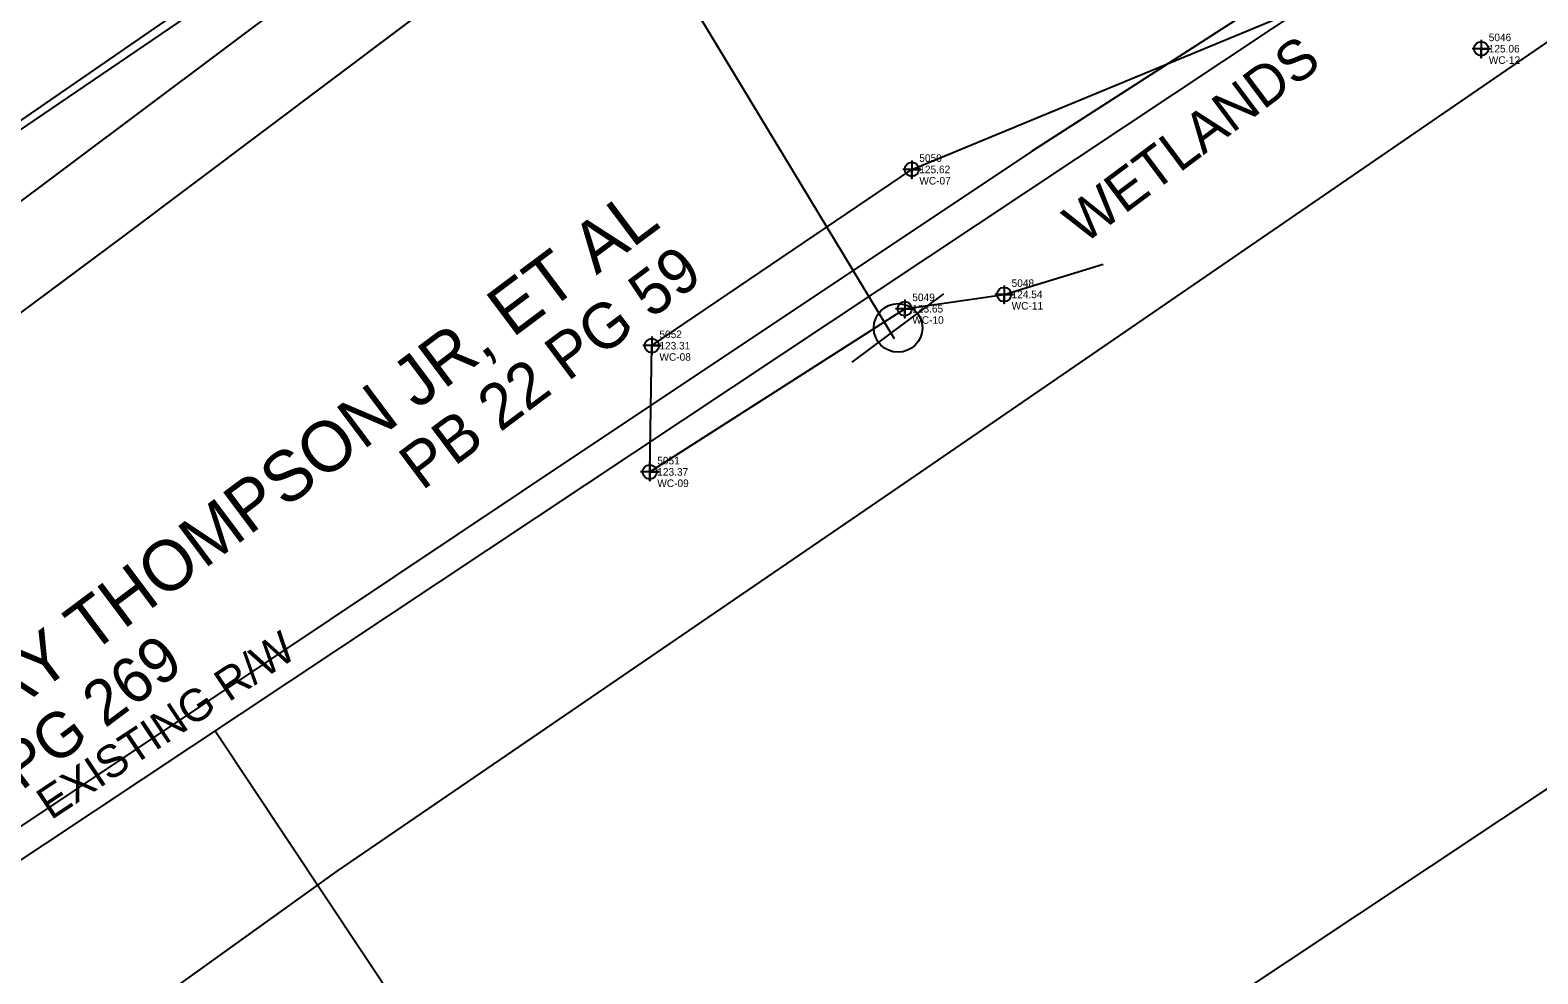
# Model space of a CAD drawing. Extents: x 2186615 to 2188822, y 629899 to 631820.
# Drawn here: x 2188154.1 to 2188303.7, y 631026.2 to 631119.9 of the extents above; entities that cross this region are included whole.
import ezdxf

# ---------------------------------------------------------------- set-up
doc = ezdxf.new("R2010")
doc.units = 0
for name, color, linetype in [('Exist Environmental Wetland Boundary', 7, 'Continuous'), ('Exist Environmental Wetland Boundary Cogo Comment', 7, 'Continuous'), ('Exist Environmental Wetland Boundary Cogo Elevation', 7, 'Continuous'), ('Exist Environmental Wetland Boundary Cogo Number', 7, 'Continuous'), ('Exist Environmental Wetland Boundary Cogo Point CELL', 7, 'Continuous'), ('Exist Environmental Wetland Boundary Text', 7, 'Continuous'), ('Exist Property Deed Book Text', 7, 'Continuous'), ('Exist Property Owner Text', 7, 'Continuous'), ('Exist Railroads Standard Gauge', 7, 'Continuous'), ('Exist Right of Way Line', 7, 'Continuous'), ('Exist Right of Way Line Text', 7, 'Continuous'), ('Exist Right of Way Width CELL', 7, 'Continuous'), ('Exist Roads EOP Text', 7, 'Continuous'), ('Exist Utilities Sanitary Sewer Forced Main SUE LOS B', 7, 'Continuous'), ('Exist Utilities Telephone Pole CELL', 7, 'Continuous'), ('Exist Utilities Telephone UG Cable SUE LOS C', 7, 'Continuous'), ('Exist Vegetation Woods Line', 7, 'Continuous'), ('Scratch_Level_1', 7, 'Continuous')]:
    doc.layers.add(name, color=color, linetype=linetype)

msp = doc.modelspace()

# ---------------------------------------------------------------- linework, layer by layer
at = {"layer": 'Exist Environmental Wetland Boundary'}
for points in [[(2188215.58, 631076.01), (2188215.79, 631088.55), (2188241.59, 631106.05), (2188283.04, 631123.21), (2188321.67, 631142.56)], [(2188215.58, 631076.01), (2188240.89, 631092.22), (2188250.75, 631093.63), (2188260.58, 631096.63)]]:
    msp.add_lwpolyline(points, dxfattribs=at)
at = {"layer": 'Exist Environmental Wetland Boundary Cogo Point CELL'}
for points in [[(2188298.11, 631118.93), (2188298.11, 631117.13), (2188298.11, 631118.03), (2188299.01, 631118.03), (2188297.21, 631118.03)], [(2188241.59, 631106.95), (2188241.59, 631105.15), (2188241.59, 631106.05), (2188242.49, 631106.05), (2188240.69, 631106.05)], [(2188250.75, 631094.53), (2188250.75, 631092.73), (2188250.75, 631093.63), (2188251.65, 631093.63), (2188249.85, 631093.63)], [(2188240.89, 631093.12), (2188240.89, 631091.32), (2188240.89, 631092.22), (2188241.79, 631092.22), (2188239.98, 631092.22)], [(2188215.79, 631089.45), (2188215.79, 631087.65), (2188215.79, 631088.55), (2188216.69, 631088.55), (2188214.89, 631088.55)], [(2188215.58, 631076.91), (2188215.58, 631075.11), (2188215.58, 631076.01), (2188216.48, 631076.01), (2188214.68, 631076.01)]]:
    msp.add_lwpolyline(points, dxfattribs=at)
for centre in [(2188298.11, 631118.03), (2188241.59, 631106.05), (2188250.75, 631093.63), (2188240.89, 631092.22), (2188215.79, 631088.55), (2188215.58, 631076.01)]:
    msp.add_circle(centre, 0.703, dxfattribs=at)
at = {"layer": 'Exist Railroads Standard Gauge'}
msp.add_line((2187893.71, 630771.38), (2188414.52, 631117.54), dxfattribs=at)
at = {"layer": 'Exist Right of Way Line'}
for p, q in [((2187154.4, 630354.1), (2188538.85, 631392.04)), ((2187850.54, 630836.34), (2188624.63, 631350.85)), ((2187850.54, 630836.34), (2188371.34, 631182.5)), ((2187850.54, 630836.34), (2188371.34, 631182.5))]:
    msp.add_line(p, q, dxfattribs=at)
at = {"layer": 'Exist Right of Way Width CELL'}
msp.add_line((2188172.46, 631050.31), (2188198.28, 631011.45), dxfattribs=at)
at = {"layer": 'Exist Utilities Sanitary Sewer Forced Main SUE LOS B'}
msp.add_lwpolyline([(2188052.08, 631035.89), (2188074.5, 631052.61), (2188093.79, 631066.37), (2188121.43, 631086.62), (2188146.17, 631105.29), (2188183, 631130.32), (2188212.25, 631151.9), (2188236.06, 631169.55), (2188274.9, 631197.79), (2188300.59, 631215.98), (2188344.72, 631249.04), (2188387.13, 631281.33), (2188437.44, 631319.58), (2188480.75, 631351.94), (2188530.77, 631388.8), (2188537.37, 631394.07)], dxfattribs=at)
at = {"layer": 'Exist Utilities Telephone Pole CELL'}
for p, q in [((2188235.69, 631086.91), (2188244.76, 631093.71)), ((2188240.23, 631090.31), (2188240.23, 631090.31))]:
    msp.add_line(p, q, dxfattribs=at)
msp.add_circle((2188240.23, 631090.31), 2.41, dxfattribs=at)
at = {"layer": 'Exist Utilities Telephone UG Cable SUE LOS C'}
for points in [[(2188239.88, 631089.23), (2188209.7, 631139.17), (2188205.31, 631145.33), (2188202.92, 631147.6), (2188200.81, 631153.01), (2188202.37, 631156.1), (2188209.69, 631162.82), (2188228.85, 631177.06), (2188268.68, 631206.68), (2188293.54, 631225.66), (2188339.11, 631259.48), (2188381.57, 631291.6), (2188431.82, 631329.3), (2188475.74, 631362.76), (2188523.99, 631399.21), (2188530.06, 631403.8)], [(2188094.37, 630991.41), (2188096.88, 630993.34), (2188087.79, 631026.43), (2188086.82, 631054.16), (2188087.06, 631058.84), (2188088.93, 631062.35), (2188093.27, 631066.84), (2188121.22, 631086.85), (2188145.88, 631105.9), (2188182.55, 631131.21), (2188212.13, 631152.41), (2188236.63, 631168.55), (2188279.23, 631192.06), (2188292.43, 631201.57), (2188302.49, 631212.36), (2188347.67, 631244.49), (2188388.98, 631278.39), (2188439.32, 631316.4), (2188482.92, 631349.33), (2188532.32, 631387.1), (2188539.16, 631391.7)]]:
    msp.add_lwpolyline(points, dxfattribs=at)
at = {"layer": 'Exist Vegetation Woods Line'}
for points in [[(2187900, 630901.47), (2187930.95, 630926.02), (2187966.57, 630951.75), (2187999.62, 630976.07), (2188035.07, 631001.76), (2188066.4, 631024.95), (2188104.74, 631054.06), (2188133.99, 631077.57), (2188163.27, 631099.35), (2188198, 631125.47), (2188236.07, 631154.15), (2188273.27, 631182), (2188303.14, 631206.11), (2188341.9, 631232.33), (2188374.15, 631253.71), (2188405.25, 631276.99)], [(2187912.42, 630863.47), (2187965.88, 630898.63), (2188006.08, 630921.31), (2188016.76, 630922.95), (2188041.27, 630935.01), (2188079.01, 630960.1), (2188134.21, 631000.22), (2188184.55, 631036.37), (2188240.85, 631074.86), (2188450.68, 631218.94)], [(2188336.81, 631162.74), (2188304.67, 631140.79), (2188253.49, 631107.84), (2188202.91, 631074.1), (2188139.41, 631031.67), (2188093.1, 631000.83), (2188032.1, 630960.3), (2187970.81, 630919.03), (2187899.6, 630870.56), (2187878.91, 630858.57), (2187866.57, 630849.5), (2187856.84, 630841.46), (2187846.68, 630832.19), (2187829.94, 630827.76), (2187807.52, 630819.83), (2187838.54, 630838.9), (2187846.29, 630845.15), (2187849.33, 630854.22), (2187863.66, 630870.01), (2187881.14, 630887.73), (2187900, 630901.47)]]:
    msp.add_lwpolyline(points, dxfattribs=at)
at = {"layer": 'Scratch_Level_1'}
msp.add_line((2187893.71, 630771.38), (2188667.8, 631285.88), dxfattribs=at)

# ---------------------------------------------------------------- texts
at = {"layer": 'Exist Environmental Wetland Boundary Cogo Comment'}
for s, p in [('WC-12', (2188298.86, 631116.53)), ('WC-07', (2188242.34, 631104.55)), ('WC-11', (2188251.5, 631092.13)), ('WC-10', (2188241.64, 631090.72)), ('WC-08', (2188216.54, 631087.05)), ('WC-09', (2188216.33, 631074.51))]:
    msp.add_text(s, height=0.75, dxfattribs=at).set_placement(p)
at = {"layer": 'Exist Environmental Wetland Boundary Cogo Elevation'}
for s, p in [('125.06', (2188298.86, 631117.66)), ('125.62', (2188242.34, 631105.67)), ('124.54', (2188251.5, 631093.26)), ('123.65', (2188241.64, 631091.84)), ('123.31', (2188216.54, 631088.17)), ('123.37', (2188216.33, 631075.64))]:
    msp.add_text(s, height=0.75, dxfattribs=at).set_placement(p)
at = {"layer": 'Exist Environmental Wetland Boundary Cogo Number'}
for s, p in [('5046', (2188298.86, 631118.78)), ('5050', (2188242.34, 631106.8)), ('5048', (2188251.5, 631094.38)), ('5049', (2188241.64, 631092.97)), ('5052', (2188216.54, 631089.3)), ('5051', (2188216.33, 631076.76))]:
    msp.add_text(s, height=0.75, dxfattribs=at).set_placement(p)
at = {"layer": 'Exist Environmental Wetland Boundary Text'}
msp.add_text('WETLANDS', height=4, rotation=36.8593, dxfattribs=at).set_placement((2188258.64, 631098.53))
at = {"layer": 'Exist Property Deed Book Text'}
for s, p in [('PB 22 PG 59', (2188192.97, 631074.09)), ('DB 3050 PG 269', (2188133.13, 631029.24))]:
    msp.add_text(s, height=4.5, rotation=36.8593, dxfattribs=at).set_placement(p)
at = {"layer": 'Exist Property Owner Text'}
msp.add_text('MORRIS RAY THOMPSON JR, ET AL', height=5, rotation=36.8593, dxfattribs=at).set_placement((2188124.68, 631031.33))
at = {"layer": 'Exist Right of Way Line Text'}
msp.add_text('EXISTING R/W', height=3.2, rotation=33.6101, dxfattribs=at).set_placement((2188156.15, 631041.39))
at = {"layer": 'Exist Roads EOP Text'}
msp.add_text("US 301/NC 96/S BRIGHTLEAF BLVD 31' BST", height=4, rotation=37.1238, dxfattribs=at).set_placement((2188076.81, 631090.07))

doc.saveas('drawing.dxf')
